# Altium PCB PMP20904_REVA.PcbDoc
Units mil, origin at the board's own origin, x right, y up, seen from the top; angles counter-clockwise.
Board outline 2450 x 1750 mil, 4 copper layers (Top Layer, Signal Layer 1, Signal Layer 2, Bottom Layer), stack 84.834 mil thick; 63 components, 24 nets, 129 pads, 79 vias.
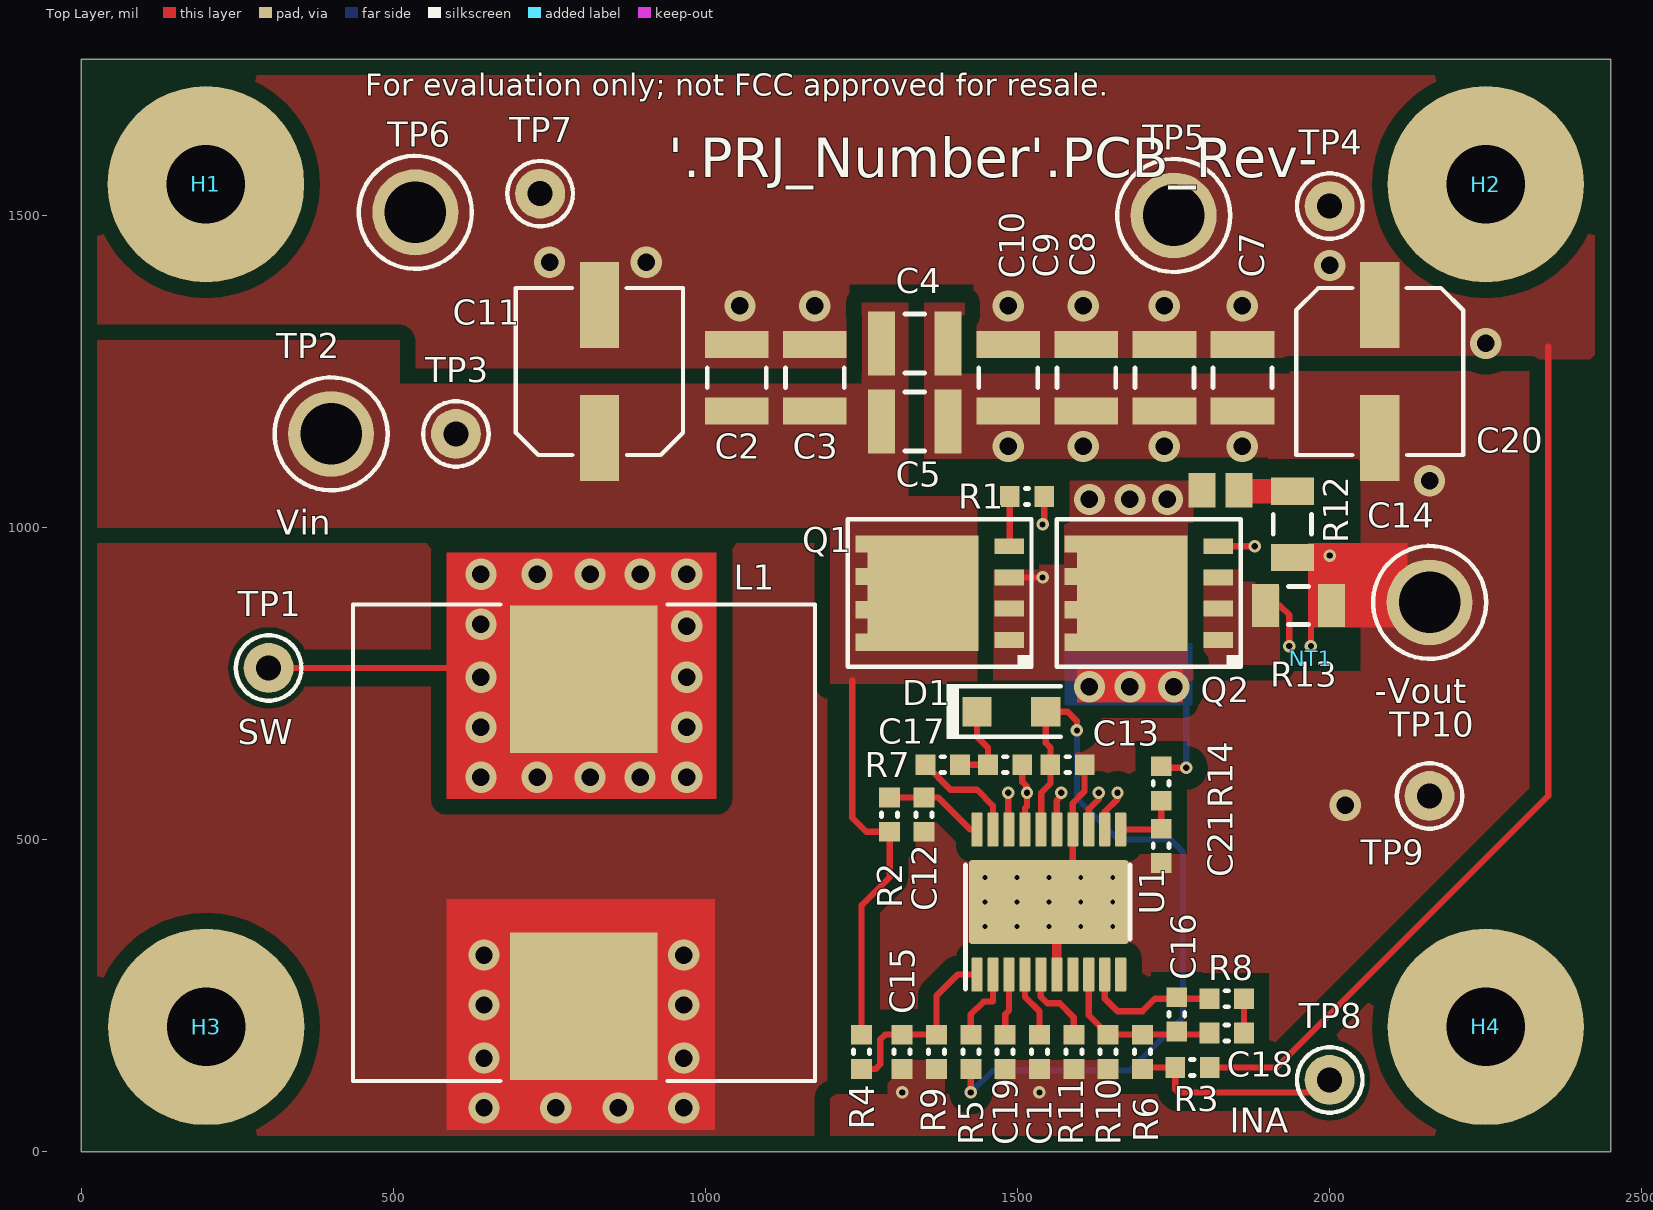
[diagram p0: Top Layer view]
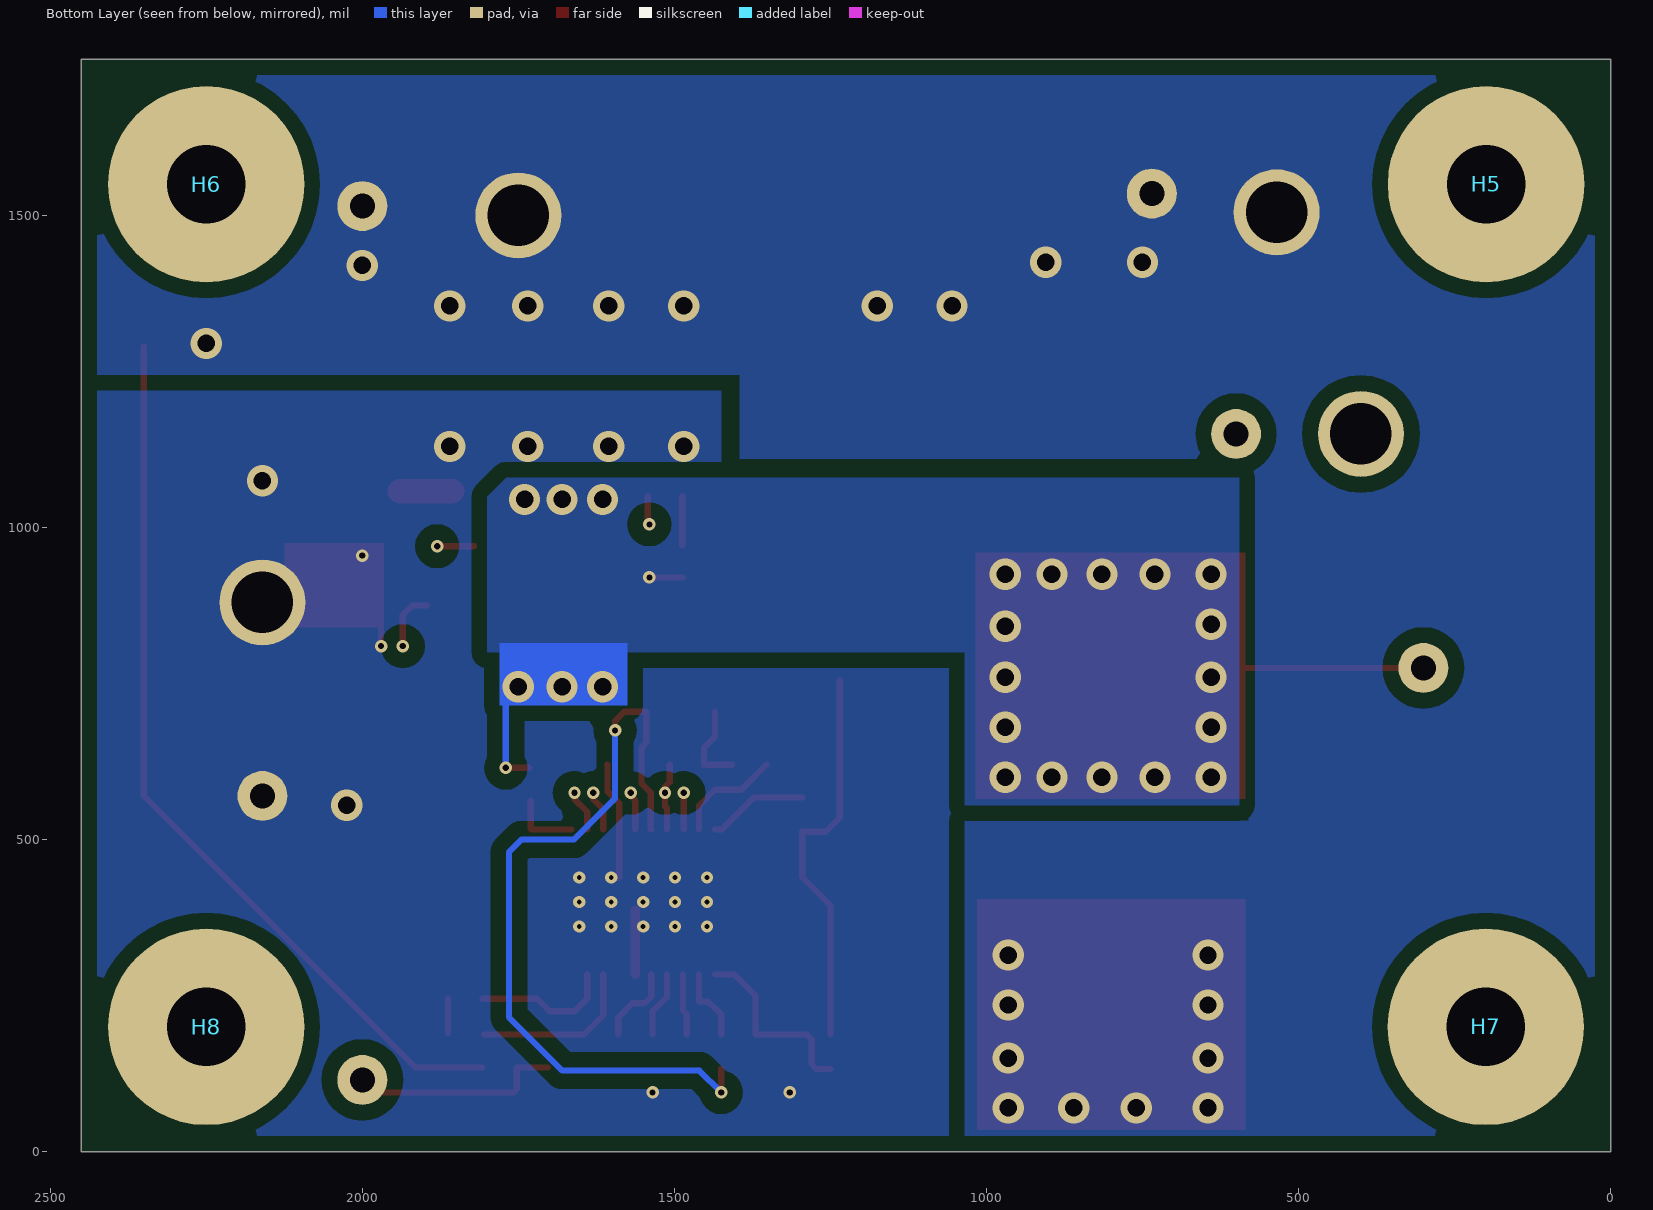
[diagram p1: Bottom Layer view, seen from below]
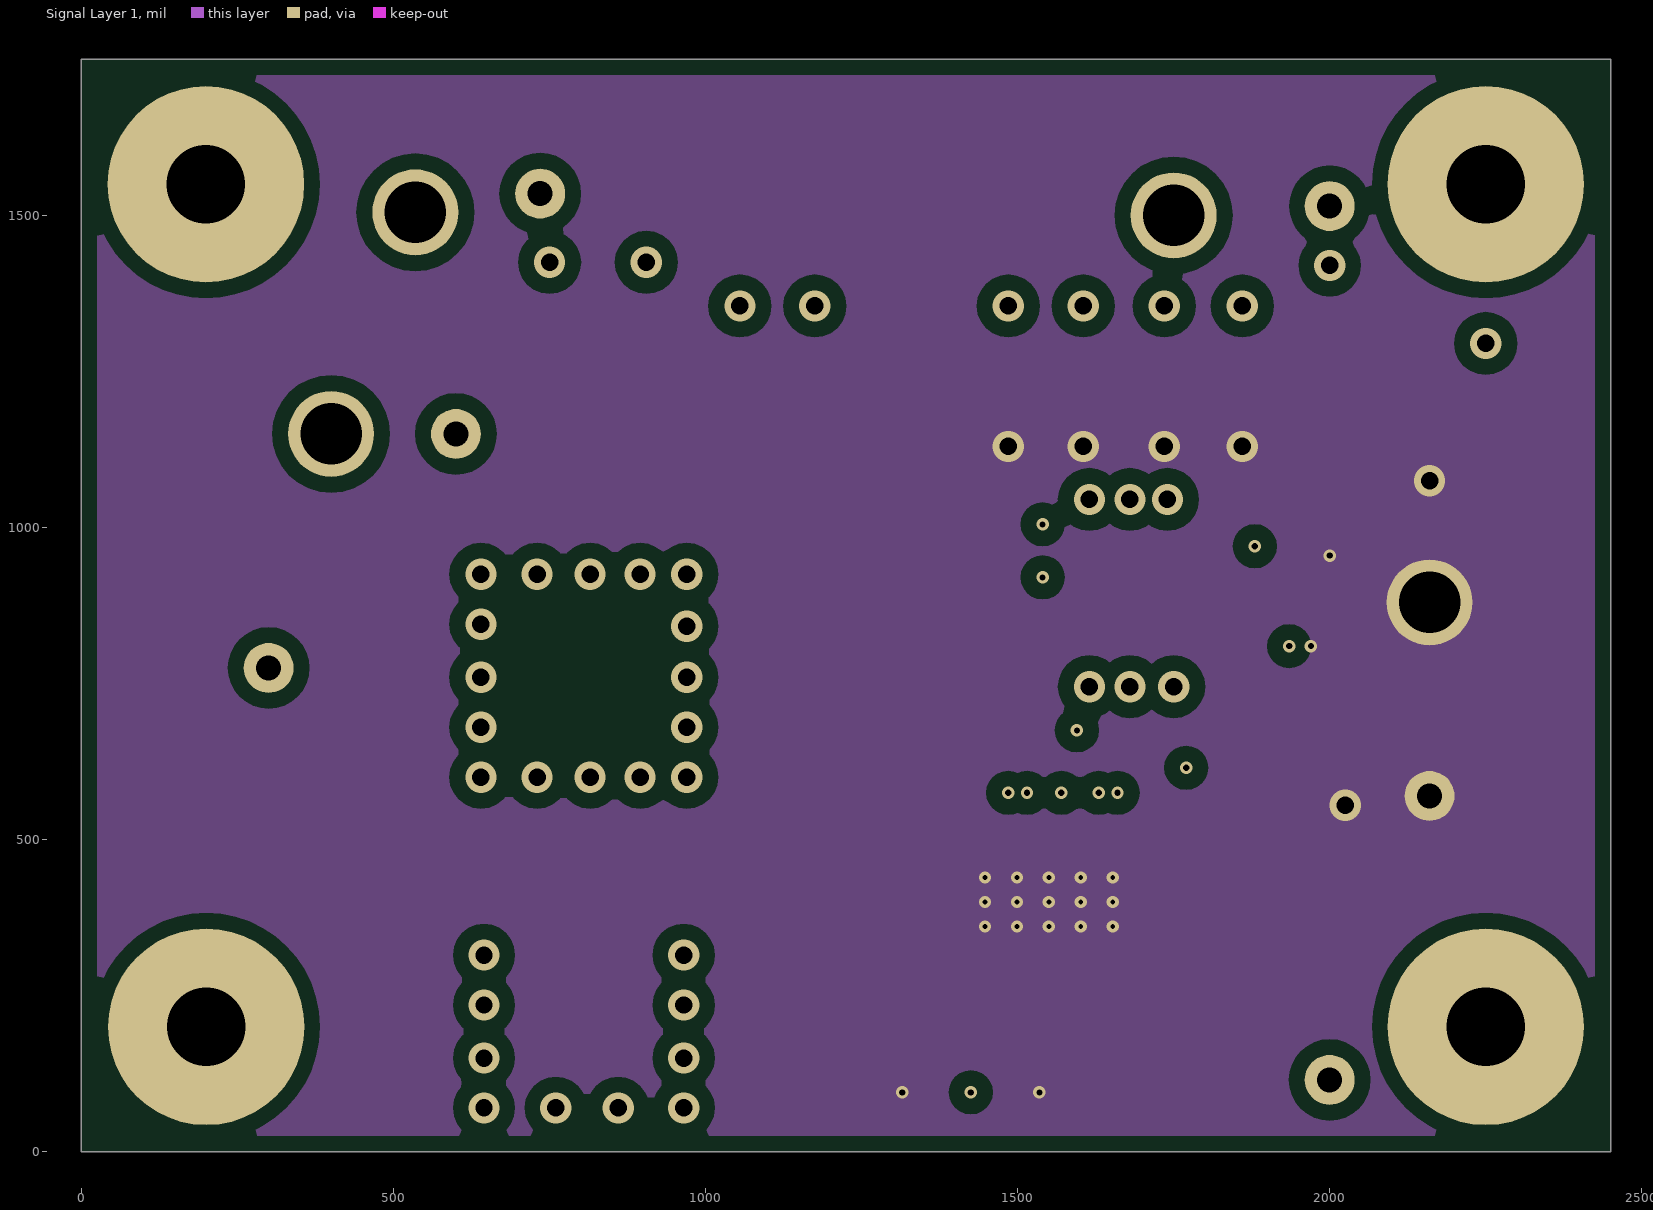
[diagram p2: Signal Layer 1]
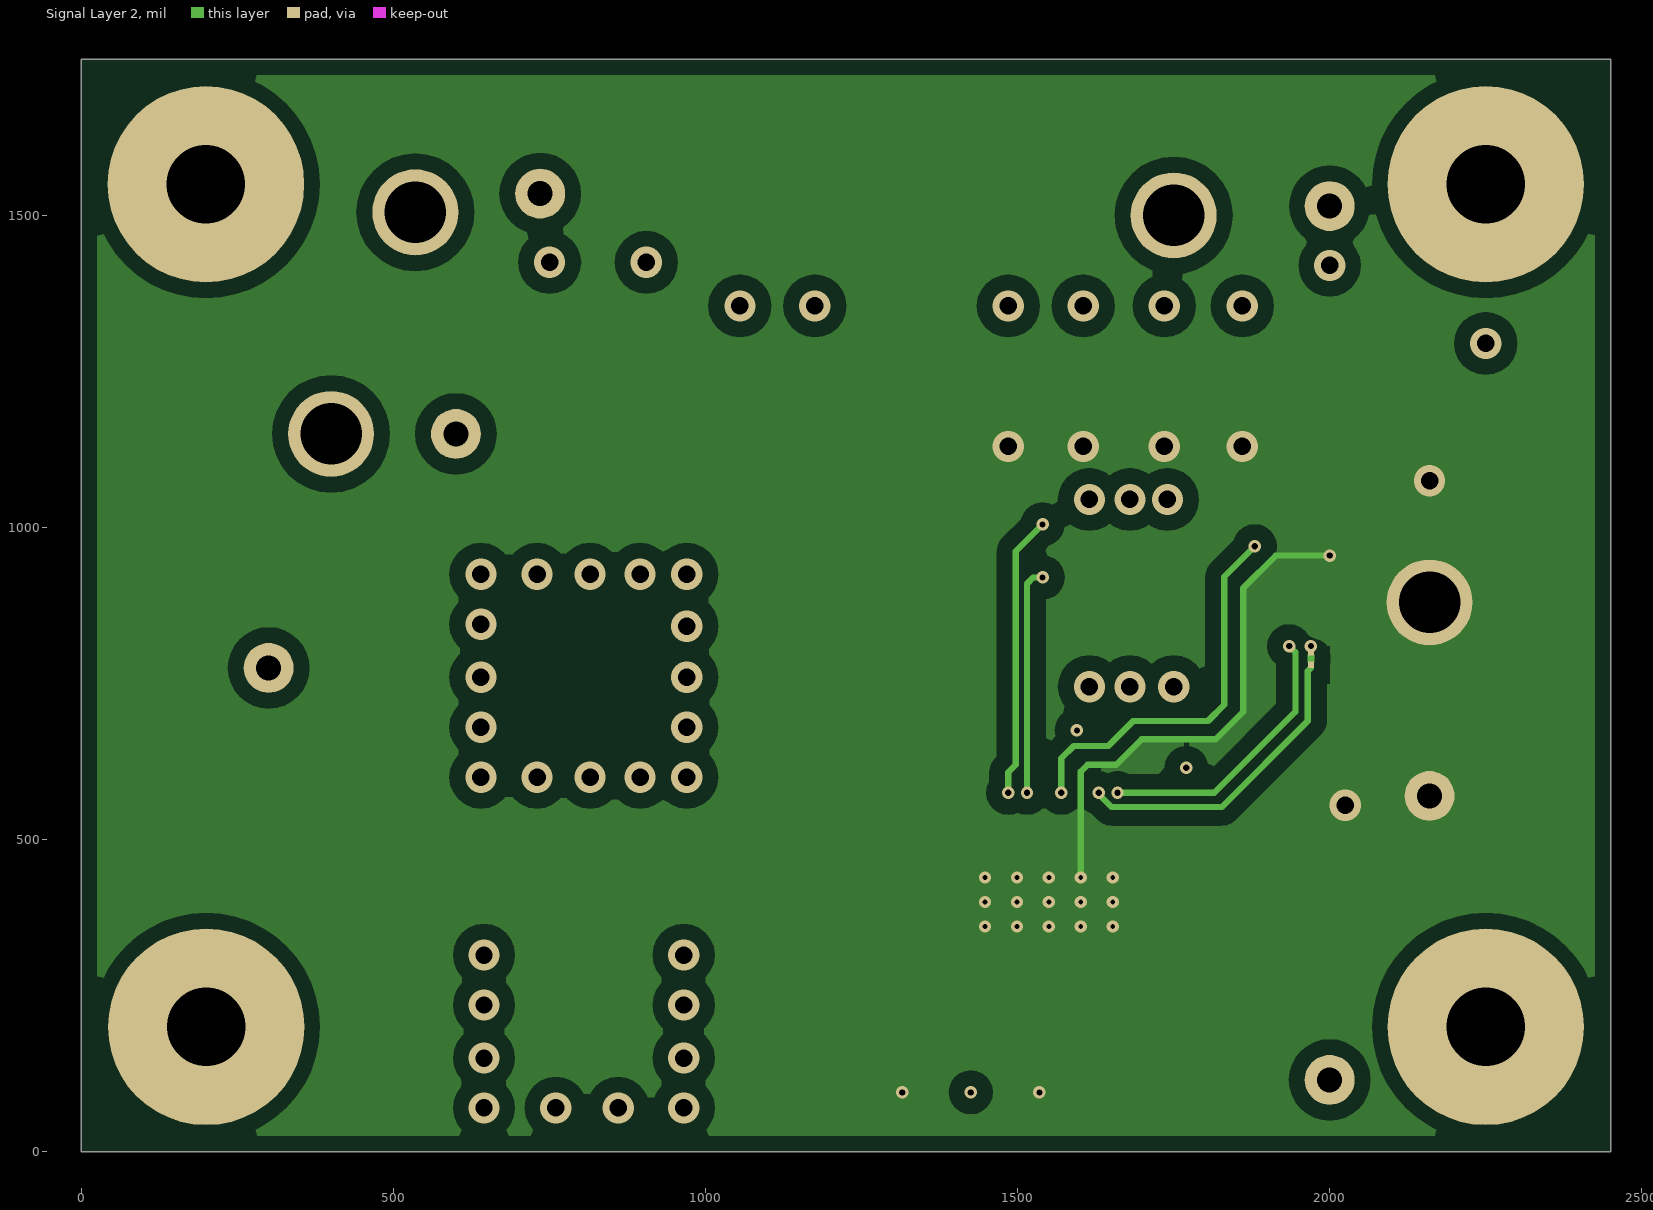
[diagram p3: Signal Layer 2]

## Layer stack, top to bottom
Top Solder: solder mask 0.4, Solder Resist, Dk 3.5
Top Layer: signal copper 1.4
Dielectric1: core 59.2, FR-4, Dk 4.8
Signal Layer 1: signal copper 1.417
Dielectric 2: dielectric 10, Dk 4.2
Signal Layer 2: signal copper 1.417
Dielectric 3: dielectric 10, Dk 4.2
Bottom Layer: signal copper 1.4
Bottom Solder: solder mask 0.4, Solder Resist, Dk 3.5

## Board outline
0,0 2450,0 2450,1750 0,1750

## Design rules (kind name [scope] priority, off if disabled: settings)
AcuteAngle [All] p1: minimum=4.50000000000000E+0001 checktracksonly=FALSE
AssemblyTestPointUsage [All] p1: valid=2
BoardOutlineClearance BoardOutlineClearance_MountingHoles [OnCopper and InComponentClass('Mounting Holes')] p1: gap=40
BoardOutlineClearance BoardOutlineClearance_Poly [OnCopper and IsPoly] p2: gap=25
BoardOutlineClearance [OnCopper and Not InComponentClass('Logo') and not InComponentClass('FiducialMark') and not InRegion(1000,500,4000,800) and not InPoly] p3: gap=75
Clearance Clearance_Keepouts [((IsTrack Or IsArc) And Not InPoly) And IsFree and IsKeepOut vs ((IsTrack Or IsArc) And Not InPoly) And IsFree and IsKeepOut] p1: gap=0
Clearance Clearance_Poly [InPolygon] p2: gap=25
Clearance [All] p3: gap=7.87
ComponentClearance ComponentClearance_MountingHoles_FiducialMarks [InComponentClass('Mounting Holes') vs InComponentClass('FiducialMark')] p1: gap=50 collisioncheckmode=3 verticalgap=10 showdistances=FALSE
ComponentClearance ComponentClearance_Shunt [InComponentClass('Header') vs InComponentClass('Shunt')] p2: gap=0 collisioncheckmode=3 verticalgap=0 showdistances=FALSE
ComponentClearance ComponentClearance_Logo [InComponentClass('Logo')] p3: gap=50 collisioncheckmode=3 verticalgap=10 showdistances=FALSE
ComponentClearance ComponentClearance_ScrewToNut [(HasFootprint('NY PMS 440 0025 PH')) vs (HasFootprint('Keystone_1902C'))] p4: gap=5 collisioncheckmode=3 verticalgap=10 showdistances=FALSE
ComponentClearance ComponentClearance_MountingHoles [InComponentClass('Mounting Holes')] p5: gap=50 collisioncheckmode=3 verticalgap=100000 showdistances=FALSE
ComponentClearance ComponentClearance_SmallPassives [HasFootprint('0201*') or HasFootprint('0402*') or HasFootprint('0508') or HasFootprint('0603*') or HasFootprint('0612') or HasFootprint('0805*') or HasFootprint('0815*') or HasFootprint('0830*') or HasFootprint('1206*') or HasFootprint('1210*') or HasFootprint('1808*') or HasFootprint('1812*') or HasFootprint('1825*') or HasFootprint('2010*') or HasFootprint('2220*') or HasFootprint('2225*') or HasFootprint('2512*') or HasFootprint('2728*') or HasFootprint('3518*') vs HasFootprint('0201*') or HasFootprint('0402*') or HasFootprint('0508') or HasFootprint('0603*') or HasFootprint('0612') or HasFootprint('0805*') or HasFootprint('0815*') or HasFootprint('0830*') or HasFootprint('1206*') or HasFootprint('1210*') or HasFootprint('1808*') or HasFootprint('1812*') or HasFootprint('1825*') or HasFootprint('2010*') or HasFootprint('2220*') or HasFootprint('2225*') or HasFootprint('2512*') or HasFootprint('2728*') or HasFootprint('3518*')] p6: gap=14.96 collisioncheckmode=3 verticalgap=10 showdistances=FALSE
ComponentClearance ComponentClearance_THtoSMT [IsThruComponent vs IsSMTComponent] p7: gap=40 collisioncheckmode=3 verticalgap=30 showdistances=FALSE
ComponentClearance ComponentClearance_THtoTH [IsThruComponent vs IsThruComponent] p8: gap=30 collisioncheckmode=3 verticalgap=30 showdistances=FALSE
ComponentClearance [All] p9: gap=30 collisioncheckmode=3 verticalgap=10 showdistances=FALSE
DiffPairsRouting [All] p1: maxlimit=100 minlimit=10 mostfreqgap=10 toplayer_minwidth=15 toplayer_maxwidth=15 toplayer_prefwidth=15 midlayer1_minwidth=15 midlayer1_maxwidth=15 midlayer1_prefwidth=15 midlayer2_minwidth=15 midlayer2_maxwidth=15 midlayer2_prefwidth=15 bottomlayer_minwidth=15 bottomlayer_maxwidth=15 bottomlayer_prefwidth=15 maxuncoupledlength=1000
FabricationTestPointUsage TestPointUsage [All] p1: valid=2 allowmultiple=FALSE
FabricationTestpoint Testpoint [All] p1: side=3 testpointundercomponent=TRUE minsize=40 maxsize=100 preferedsize=60 minholesize=0 maxholesize=40 preferedholesize=32 testpointgrid=1 allowsidetop=TRUE allowsidebottom=TRUE usegrid=TRUE gridtolerance=0.01
FanoutControl Fanout_LCC [IsLCC] p1: bgadir=Out bgaviamode=Centered fanoutstyle=Auto fanoutdirection=Alternating viagrid=1 // Fanout_LCC (Default Rule)
FanoutControl Fanout_BGA [IsBGA] p2: bgadir=Out bgaviamode=Centered fanoutstyle=Auto fanoutdirection=Alternating viagrid=1 // Fanout_BGA (Default Rule)
FanoutControl Fanout_Default [All] p4: bgadir=Out bgaviamode=Centered fanoutstyle=Auto fanoutdirection=Alternating viagrid=1 // Fanout_Default (Default Rule)
FanoutControl Fanout_Small [(CompPinCount < 5)] p5: bgadir=Out bgaviamode=Centered fanoutstyle=Auto fanoutdirection=OutThenIn viagrid=1 // Fanout_Small (Default Rule)
HoleSize [All] p1: absolutevalues=TRUE maxlimit=251 minlimit=7.87 maxpercent=80.000 minpercent=20.000
MinimumAnnularRing MinimumAnnularRing_ThermalPadVias [IsVia and InAnyComponent] p1: minimumring=5
MinimumAnnularRing [All] p2: minimumring=4.99
MinimumSolderMaskSliver MinimumSolderMaskSliver_Logo [InComponentClass('Logo') vs InComponentClass('Logo')] p1: minsoldermaskwidth=0.7
MinimumSolderMaskSliver [All] p2: minsoldermaskwidth=3.94
PlaneConnect [All] p1: planeconnectstyle=Direct reliefexpansion=10 reliefentries=4 reliefconductorwidth=10 reliefairgap=10
PolygonConnect [All] p1: connectstyle=Direct reliefconductorwidth=10 reliefentries=4 polygonreliefangle="90 Angle" airgapwidth=10
RoutingVias ThermalPadVias [IsVia and InAnyComponent] p1: holewidth=7.87 width=19.68 viastyle="Through Hole" minholewidth=7.87 minwidth=19.68 maxholewidth=12.99 maxwidth=23.62
RoutingVias [All] p2: holewidth=16 width=34 viastyle="Through Hole" minholewidth=7.87 minwidth=26 maxholewidth=40 maxwidth=65
SilkToBoardRegionClearance [Not ((IsComment or IsDesignator) And (Hide <> 'False')) and not InRegion(1000,500,4000,800)] p1:
SilkToSilkClearance SilkToSilkClearance_Pb-FreeLogo [(HasFootprint('Pb-Free_Overlay_Medium') OR HasFootprint('Pb-Free_Overlay_Small')) vs (HasFootprint('Pb-Free_Overlay_Medium') OR HasFootprint('Pb-Free_Overlay_Small'))] p1: silktosilkclearance=0
SilkToSilkClearance [All] p2: silktosilkclearance=4
SilkToSolderMaskClearance SilkToComponentPadClearance [(IsPad or IsFill or IsRegion) and InAnycomponent] p1: minsilkscreentomaskgap=5 clearancetoexposedcopper=TRUE
SilkToSolderMaskClearance "Silk to Solder Mask Opening" [All] p2: minsilkscreentomaskgap=4 clearancetoexposedcopper=FALSE
SolderMaskExpansion [All] p1: expansion=1.97
Width [All] p1: maxlimit=100 minlimit=6 preferedwidth=10 checkconnectedcopper=TRUE
15 further rules are at their usual default settings.

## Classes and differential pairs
component class PMP20904_REVA: C1 C2 C3 C4 C5 C7 C8 C9 C10 C11 C12 C13 C14 C15 C16 C17 C18 C19 C20 C21 D1 L1 NT1 Q1 Q2 R1 R2 R3 R4 R5 R6 R7 R8 R9 R10 R11 R12 R13 R14 TP1 TP2 TP3 TP4 TP5 TP6 TP7 TP8 TP9 TP10 U1
component class AssemblyNote: ZZ1 ZZ2 ZZ3 ZZ4
component class PMP20904_REVA_Hardware: H1 H2 H3 H4 H5 H6 H7 H8 Logo2 ZZ1 ZZ2 ZZ3 ZZ4
component class "Mounting Holes": H1 H2 H3 H4

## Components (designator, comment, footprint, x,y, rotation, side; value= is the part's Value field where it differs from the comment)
C1 "GRM188R71E104KA01D" 0603L 1535,160 r270 top
C2 "UMK325AB7106KM-T" 1210L 1050,1240 r90 top
C3 "UMK325AB7106KM-T" 1210L 1175,1240 r90 top
C4 "GRM32ER71K475KE14L" 1210L 1335,1295 r0 top
C5 "GRM32ER71K475KE14L" 1210L 1335,1170 r0 top
C7 "UMK325AB7106KM-T" 1210L 1860,1240 r270 top
C8 "UMK325AB7106KM-T" 1210L 1735,1240 r270 top
C9 "UMK325AB7106KM-T" 1210L 1610,1240 r270 top
C10 "UMK325AB7106KM-T" 1210L 1485,1240 r270 top
C11 "UUD1V680MCL1GS" SM_RADIAL_6.3BMM 830,1250 r90 top
C12 "CGA3E3X7R1H474M080AE" 0603L 1350,540 r270 top
C13 "GRM188R71C105KE15D" 0603L 1580,620 r0 top
C14 "DNP" 0805L 1825,1060 r0 top
C15 "GRM1885C1H470JA01D" 0603L 1315,160 r270 top
C16 "GRM188R71H472KA01D" 0603L 1755,220 r90 top
C17 "CGA3E3X7R1H474M080AE" 0603L 1480,620 r0 top
C18 "GRM188R71H473KA61D" 0603L 1835,190 r0 top
C19 "CGA3E3X7R1H474M080AE" 0603L 1480,160 r270 top
C20 "UUD1V680MCL1GS" SM_RADIAL_6.3BMM 2080,1250 r270 top
C21 "GRM1885C1H821JA01D" 0603L 1730,490 r270 top
D1 "PMEG6010CEH,115" SOD-123F 1490,705 r0 top
H1 "NY PMS 440 0025 PH" "NY PMS 440 0025 PH" 199.47,1550 r0 top locked
H2 "NY PMS 440 0025 PH" "NY PMS 440 0025 PH" 2250,1550 r0 top locked
H3 "NY PMS 440 0025 PH" "NY PMS 440 0025 PH" 200,200 r0 top locked
H4 "NY PMS 440 0025 PH" "NY PMS 440 0025 PH" 2250,200 r0 top locked
H5 "1902C" Keystone_1902C 199.47,1550 r180 bottom locked
H6 "1902C" Keystone_1902C 2250,1550 r180 bottom locked
H7 "1902C" Keystone_1902C 200,200 r180 bottom locked
H8 "1902C" Keystone_1902C 2250,200 r180 bottom locked
L1 "74435571500" WE-HCB_1890 805,495 r270 top
Logo2 "FCC disclaimer" FCC_disclaimer 2350,3380 r0 top
NT1 "Net-Tie" Net-Tie_10mil 1970,790 r270 top net-tie
Q1 "BSC097N06NSATMA1" PG-TDSON-8 1375,895 r180 top
Q2 "BSC097N06NSATMA1" PG-TDSON-8 1710,895 r180 top
R1 "CRCW06030000Z0EA" 0603L 1515,1050 r180 top
R2 "CRCW06033R90JNEA" 0603L 1295,540 r270 top
R3 "CRCW06038R06FKEA" 0603L 1780,135 r0 top
R4 "CRCW060349K9FKEA" 0603L 1250,160 r90 top
R5 "DNP" 0603L 1425,160 r90 top
R6 "CRCW06035K11FKEA" 0603L 1700,160 r270 top
R7 "CRCW06030000Z0EA" 0603L 1380,620 r180 top
R8 "CRCW06032K55FKEA" 0603L 1835,245 r0 top
R9 "CRCW06033K32FKEA" 0603L 1370,160 r90 top
R10 "CRCW0603174RFKEA" 0603L 1645,160 r90 top
R11 "CRCW060312K1FKEA" 0603L 1590,160 r90 top
R12 "DNP" 1206L#1 1940,1025 r90 top
R13 "WSL12068L000FEA" 1206L#2 1950,875 r180 top
R14 "CRCW0603232KFKEA" 0603L 1730,590 r90 top
TP1 "SW" Keystone5002 300,775 r90 top
TP2 "Vin" Keystone1502-2 400,1150 r0 top
TP3 "Vin" Keystone5000 600,1150 r90 top
TP4 "GND" Keystone5001 2000,1515 r90 top
TP5 "GND" Keystone1502-2 1750,1500 r0 top
TP6 "GND" Keystone1502-2 535,1505 r0 top
TP7 "GND" Keystone5001 735,1535 r90 top
TP8 "INA" Keystone5002 2000,115 r90 top
TP9 "-Vout" Keystone5000 2160,570 r90 top
TP10 "-Vout" Keystone1502-2 2160,880 r0 top
U1 "LM5117PMHX/NOPB" PWP0020A_N 1550,400 r90 top
ZZ1 "This Assembly Note is for PCB labels only" AssemblyNoteLabel 185,3938 r0 top
ZZ2 "These assemblies are ESD sensitive, ESD precautions shall be observed." AssemblyNote 185,3829.11 r0 top
ZZ3 "These assemblies must be clean and free from flux and all contaminants. Use of no clean flux is not acceptable." AssemblyNote 185,3740.56 r0 top
ZZ4 "These assemblies must comply with workmanship standards IPC-A-610 Class 2, unless otherwise specified." AssemblyNote 185,3652 r0 top

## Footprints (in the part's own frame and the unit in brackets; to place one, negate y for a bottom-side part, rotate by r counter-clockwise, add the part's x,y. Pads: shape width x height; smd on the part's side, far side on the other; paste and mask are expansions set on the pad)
0603L [mm] "0603 from SM-752 data"
  rect 0.8x0.85 smd: 1(-0.7,0) 2(0.7,0)
  silkscreen extent -0.07,-0.33 0.07,0.33, body extent -0.87,-0.47 0.87,0.47, height 1
0805L [mm] "0805 from SM-752 data"
  rect 1.1x1.4 smd: 1(-0.75,0) 2(0.75,0)
  body extent -1.1,-0.72 1.1,0.72, height 1.45
1206L#1 [mm] "1206 from SM-752 data"
  rect 1.1x1.75 smd: 1(-1.858,0) 2(0.842,0)
  silkscreen extent -0.91,-0.77 -0.11,0.77, body extent -2.21,-0.9 1.19,0.9, height 1.35
1206L#2 [mm] "1206 from SM-752 data"
  rect 1.1x1.75 smd: 1(-1.35,0) 2(1.35,0)
  silkscreen extent -0.4,-0.77 0.4,0.77, body extent -1.7,-0.9 1.7,0.9, height 1.35
1210L [mm] "1210 from SM-752 data"
  rect 1.1x2.6 smd: 1(-1.35,0) 2(1.35,0)
  silkscreen extent -0.4,-1.2 0.4,1.2, body extent -1.7,-1.35 1.7,1.35, height 1.35
AssemblyNote [mil] "Assembly Note"
AssemblyNoteLabel [mil] "Assembly Note for PCB Labels"
FCC_disclaimer [mil]
Keystone1502-2 [mm] "Double Turret"
  round 3.5 hole 2.5: 1(0,0)
  silkscreen extent -2.3,-2.3 2.3,2.3, body extent -1.6,-1.6 1.59,1.6, height 5.62
Keystone5000 [mil] "For Keystone 500x miniature loop terminals"
  round 80 hole 40: 1(0,0)
  silkscreen extent -52,-52 52,52, body extent -49,-49 49,49, height 182
Keystone5001 [mil] "For Keystone 500x miniature loop terminals"
  round 80 hole 40: 1(0,0)
  silkscreen extent -52,-52 52,52, body extent -49,-49 49,49, height 182
Keystone5002 [mil] "For Keystone 500x miniature loop terminals"
  round 80 hole 40: 1(0,0)
  silkscreen extent -52,-52 52,52, body extent -49,-49 49,49, height 182
Keystone_1902C [mil] "Hex Standoff, 4-40 threaded, nylon"
  body extent -145,-126 146,126, height 501
Net-Tie_10mil [mil] "10mil net tie, no solder mask opening, no solder paste"
  rect 10x10 on Mid2 paste-5 mask-5: 1(-10,0) 2(10,0)
  Signal Layer 2 region: -6,5 6,5 6,-5 -6,-5
"NY PMS 440 0025 PH" [mm] "4-40 nylon screw and mounting hole"
  round 8 hole 3.2: 1(0,0)
  body extent -3.3,-3.3 3.3,3.3, height 2.69
PG-TDSON-8 [mm] "Infineon recommended land pattern"
  rect 1.2x0.65 smd: 1(-2.825,1.905) 2(-2.825,0.635) 3(-2.825,-0.635) 4(-2.825,-1.905)
  rect 0.5x0.7 smd: 5(3.175,-2) 6(3.175,-0.675) 7(3.175,0.675) 8(3.175,2)
  rect 4.5x4.7 smd paste-2.25: 9(0.675,0)
  silkscreen extent -3.74,-3 3.74,3, body extent -3.18,-2.89 3.18,2.9, height 1.1
PWP0020A_N [mm] "TSOP, 20-Leads, Body 6.5x4.4mm, Pitch 0.65mm, Exposed Pad, IPC Medium Density"
  rrect22% 1.4x0.45 smd: 1(-2.95,2.925) 2(-2.95,2.275) 3(-2.95,1.625) 4(-2.95,0.975) 5(-2.95,0.325) 6(-2.95,-0.325) 7(-2.95,-0.975) 8(-2.95,-1.625) 9(-2.95,-2.275) 10(-2.95,-2.925) 11(2.95,-2.925) 12(2.95,-2.275) 13(2.95,-1.625) 14(2.95,-0.975) 15(2.95,-0.325) 16(2.95,0.325) 17(2.95,0.975) 18(2.95,1.625) 19(2.95,2.275) 20(2.95,2.925)
  rrect6% 3.4x6.5 smd paste-2 mask-2: 21(0,0)
  rrect3% 3.15x4.35 on Top Paste: 21(0,0)
  rrect3% 3.15x4.35 on Top Solder: 21(0,0)
  silkscreen extent -3.55,-3.3 1.5,3.4, body extent -3.21,-3.25 3.21,3.25, height 1
SM_RADIAL_6.3BMM [mm] "Nichicon 6.3x7.7"
  rect 3.5x1.6 smd: 1(-2.7,0) 2(2.7,0)
  silkscreen extent -3.4,-3.4 3.4,3.4, body extent -3.4,-3.4 3.4,3.4, height 8
SOD-123F [mm] "NXP recommended land pattern"
  rect 1.2x1.2 smd paste-0.05: 1(-1.4,0) 2(1.4,0)
  silkscreen extent -2.64,-1.12 2.01,1.12, body extent -1.8,-0.85 1.8,0.85, height 1.2
WE-HCB_1890 [mm] "WURTH ELEKTRONIK"
  rect 6x6 smd: 1(-6.65,0) 2(6.65,0)
  silkscreen extent -9.7,-9.4 9.7,9.4, body extent -9.65,-9.35 9.65,9.35, height 9.2

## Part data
C1: "CAP, CERM, 0.1 µF, 25 V, +/- 10%, X7R, 0603"
C2 C3 C7 C8 C9 C10: "CAP, CERM, 10 µF, 50 V, +/- 10%, X7R, 1210"
C4 C5: "CAP, CERM, 4.7 µF, 80 V, +/- 10%, X7R, 1210"
C11 C20: "CAP, AL, 68 µF, 35 V, +/- 20%, 0.34 ohm, SMD"
C12 C17 C19: "CAP, CERM, 0.47 µF, 50 V, +/- 20%, X7R, AEC-Q200 Grade 1, 0603"
C13: "CAP, CERM, 1 µF, 16 V, +/- 10%, X7R, 0603"
C14: library part GRM2165C2A101JA01D, "CAP, CERM, 100 pF, 100 V, +/- 5%, C0G/NP0, 0805"
C15: "CAP, CERM, 47 pF, 50 V, +/- 5%, C0G/NP0, 0603"
C16: "CAP, CERM, 4700 pF, 50 V, +/- 10%, X7R, 0603"
C18: "CAP, CERM, 0.047 µF, 50 V, +/- 10%, X7R, 0603"
C21: "CAP, CERM, 820 pF, 50 V, +/- 5%, C0G/NP0, 0603"
D1: "Diode, Schottky, 60 V, 1 A, SOD-123F"
H1 H2 H3 H4: "Machine Screw, Round, #4-40 x 1/4, Nylon, Philips panhead"
H5 H6 H7 H8: "Standoff, Hex, 0.5\"L #4-40 Nylon"
L1: "Inductor, Shielded Drum Core, Ferrite, 15 µH, 14 A, 0.009 ohm, SMD"
Logo2: library part FCC_disclaimer, "FCC_disclaimer"
NT1: "Single point connection between nets."
Q1 Q2: "MOSFET, N-CH, 60 V, 46 A, PG-TDSON-8"
R1 R7: "RES, 0, 5%, 0.1 W, 0603"
R2: "RES, 3.9, 5%, 0.1 W, 0603"
R3: "RES, 8.06, 1%, 0.1 W, 0603"
R4: "RES, 49.9 k, 1%, 0.1 W, 0603"
R5: library part CRCW060349K9FKEA, "RES, 49.9 k, 1%, 0.1 W, 0603"
R6: "RES, 5.11 k, 1%, 0.1 W, 0603"
R8: "RES, 2.55 k, 1%, 0.1 W, 0603"
R9: "RES, 3.32 k, 1%, 0.1 W, 0603"
R10: "RES, 174, 1%, 0.1 W, 0603"
R11: "RES, 12.1 k, 1%, 0.1 W, 0603"
R12: library part CRCW120610R0JNEA, "RES, 10, 5%, 0.25 W, 1206"
R13: "RES, 0.008, 1%, 0.25 W, AEC-Q200 Grade 0, 1206"
R14: "RES, 232 k, 1%, 0.1 W, 0603"
TP1 TP8: library part 5002, "Test Point, TH, Miniature, White"
TP2 TP5 TP6 TP10: library part 1502-2, "Terminal, Turret, TH, Double"
TP3 TP9: library part 5000, "Test Point, TH, Miniature, Red"
TP4 TP7: library part 5001, "Test Point, TH, Miniature, Black"
U1: "5.5-65V Wide Vin, Current Mode Synchronous Buck Controller with Analog Current Monitor, PWP0020A (TSSOP-20)"
ZZ1: library part AssemblyNoteLabel
ZZ2 ZZ3 ZZ4: library part AssemblyNote

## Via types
v1: diameter 50, hole 28, Top Layer to Bottom Layer, 48 vias
v2: diameter 20, hole 10, Top Layer to Bottom Layer, 16 vias
v3: diameter 19.68, hole 7.87, Top Layer to Bottom Layer, 9 vias
v4: diameter 19.68, hole 7.87, Top Layer to Bottom Layer, tented both sides, 6 vias

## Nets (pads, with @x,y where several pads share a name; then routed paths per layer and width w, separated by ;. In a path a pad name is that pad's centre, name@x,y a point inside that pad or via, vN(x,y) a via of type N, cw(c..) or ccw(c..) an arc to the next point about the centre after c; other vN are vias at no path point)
-VOUT: C1.2 C4.2 C5.2 C7.2 C8.2 C9.2 C10.2 C12.2 C13.2 C15.2 C19.2 C20.2 C21.2 NT1.1 R9.1 R10.1 R11.1 R12.1 R13.1 TP9.1 TP10.1 U1.6 U1.14 U1.21@1550,400 | length 1213
  Top Layer w10: U1.21@1588.39,438.39 U1.14 1588.39,558.39 1607.13,577.13 1607.13,619.57 C13.2 ; v2(1970,810) 1970,865 1980,875 R13.1
  Top Layer w15: U1.6 U1.21@1562.8,387.2
  Signal Layer 2 w10: v3(1601.18,439.37) 1601.18,609.06 1612.13,620 1657.79,620 1698.56,660.77 1817.11,660.77 1861.32,704.99 1861.32,903.1 1913.22,955 v2(2000,955)
  other v1: 2025,555 2160,1075 1485,1130 1605,1130 1735,1130 1860,1130
  other v2: 1315,95 1535,95
  other v3: 1498.82,360.63 1550,360.63 1601.18,360.63 1498.82,400 1550,400 1601.18,400 1498.82,439.37 1550,439.37
  other v4: 1447.64,360.63 1652.36,360.63 1447.64,400 1652.36,400 1447.64,439.37 1652.36,439.37
COMP: C16.2 R8.1 U1.9 | length 223
  Top Layer w10: U1.9 1639.57,245.43 1660,225 1700,225 1720,245 R8.1
CS: Q2.1 Q2.2 Q2.3 R13.2 U1.12 | length 609.7
  Top Layer w10: U1.12 1639.57,544.57 1660,565 v2(1660,575) ; R13.2 1920,875 1935,860 v2(1935,810)
  Signal Layer 2 w10: v2(1660,575) 1815,575 1945,705 1945,800 v2(1935,810)
CSG: NT1.2 U1.13 | length 560.5
  Top Layer w10: U1.13 1613.98,548.98 1630,565 v2(1630,575)
  Signal Layer 2 w10: v2(1630,575) 1630,572.65 1650.53,552.13 1827.13,552.13 1965,690 1965,770 1970,775 NT1.2
DEMB: R5.2 U1.2 | length 119.8
  Top Layer w10: R5.2 1425,220 1445.43,240.43 1460.43,240.43 U1.2
FB: C16.1 C18.1 R6.1 R10.2 U1.8 | length 269.1
  Top Layer w10: U1.8 1613.98,218.58 R10.2 R6.1 C18.1@1805,187.56
GND: C2.2 C3.2 C7.1 C8.1 C9.1 C10.1 C11.2 C20.1 L1.2 R3.2 TP4.1 TP5.1 TP6.1 TP7.1 | length 1442.6
  Top Layer w10: R3.2 1915,135 2350,570 2350,1290
  other v1: 645,70 760,70 860,70 965,70 645,150 965,150 645,235 965,235 645,315 965,315 2250,1295 1055,1355 1175,1355 1485,1355 1605,1355 1735,1355 1860,1355 2000,1420 750,1425 905,1425
HB: R7.2 U1.19 | length 173.5
  Top Layer w10: R7.2 1392.44,580 1435,580 1460.43,554.57 U1.19
HO: R1.1 U1.18 | length 556.7
  Top Layer w10: U1.18@1485,517.17 v2(1485,575) ; v2(1540,1005) 1542.56,1007.56 R1.1
  Signal Layer 2 w10: v2(1485,575) 1485,607.87 1497.13,620 1497.13,962.13 v2(1540,1005)
INA: R3.1 R6.2 TP8.1 | length 342.8
  Top Layer w10: R6.2@1702.56,135 R3.1 1752.44,100 1757.44,95 1980,95 TP8.1
LO: Q2.4 U1.15 | length 746.5
  Top Layer w10: U1.15 1562.8,562.8 1570,570 v2(1570,575) ; Q2.4 v2(1880,970)
  Signal Layer 2 w10: v2(1570,575) 1570,630 1590,650 1645,650 1685,690 1805,690 1831.06,716.06 1831.06,921.06 v2(1880,970)
NetC12_1: C12.1 R2.1 U1.20 | length 161.1
  Top Layer w10: R2.1 C12.1 1372.44,567.56 1423.86,516.14 U1.20
NetC14_2: C14.2 R12.2 | length 83.6
  Top Layer w40: C14.2@1856.38,1058.15 R12.2
NetC17_1: C17.1 D1.1 R7.1 | length 137.2
  Top Layer w10: R7.1 C17.1 1452.44,647.56 1434.88,665.12 D1.1
NetC18_2: C18.2 R8.2 | length 55
  Top Layer w10: C18.2 R8.2
NetQ1_4: Q1.4 R1.2 | length 78.8
  Top Layer w10: Q1.4@1487.44,971.22 R1.2
RAMP: C21.1 R14.1 U1.11 | length 110.3
  Top Layer w10: U1.11 1728.58,516.14 C21.1 R14.1
RES: C19.1 U1.3 | length 98.8
  Top Layer w10: C19.1 1480,220 1486.02,226.02 U1.3
RT: R11.2 U1.5 | length 129.7
  Top Layer w10: U1.5 1537.2,248.07 1547.64,237.64 1567.36,237.64 1590,215 R11.2
SS: C1.1 U1.4 | length 106
  Top Layer w10: U1.4 1511.61,248.39 1535,225 C1.1
SW: C14.1 C17.2 L1.1 Q1.1 Q1.2 Q1.3 Q2.5 Q2.6 Q2.7 Q2.8 Q2.9 R14.2 TP1.1 U1.17 | length 998.7
  Top Layer w10: TP1.1 v1@625,775 ; Q1.3 v2(1540,920) ; C17.2 1507.56,592.44 1515,585 v2(1515,575) 1515,553.54 1511.61,550.16 U1.17 ; R14.2@1732.56,615 v2(1770,615)
  Signal Layer 2 w10: v2(1515,575) 1515,910 1525,920 v2(1540,920)
  Bottom Layer w10: v2(1770,615) 1770,725
  other v1: 640,600 730,600 815,600 895,600 970,600 640,680 970,680 1615,745 1680,745 1750,745 640,760 970,760 970,841.89 640,845 640,925 730,925 815,925 895,925 970,925 1615,1045 1680,1045 1740,1045
UVLO: C15.1 R4.1 R9.2 U1.1 | length 307.6
  Top Layer w10: R4.1 1272.44,132.44 1280,140 1280,180 1287.56,187.56 R9.2 1370,250 1403.86,283.86 U1.1
VCC: C13.1 D1.2 R5.1 U1.16 | length 1275.6
  Top Layer w10: v2(1425,95) R5.1 ; U1.16 1537.87,516.81 1537.87,575.22 1552.44,589.79 C13.1 1552.44,647.56 1545.12,654.88 D1.2 1580,705 1595,690 v2(1595,675)
  Bottom Layer w10: v2(1425,95) 1460,130 1679.37,130 1765,215.63 1765,480 1745,500 1661.13,500 1595,566.13 v2(1595,675)
VIN: C2.1 C3.1 C4.1 C5.1 C11.1 Q1.5 Q1.6 Q1.7 Q1.8 Q1.9 R2.2 R4.2 TP2.1 TP3.1 | length 632.9
  Top Layer w10: 1235,755 1235,535 1257.56,512.44 R2.2 1295,440 1250,395 R4.2
pads on no net: H1.1 H2.1 H3.1 H4.1 U1.7 U1.10 U1.21@1550,400

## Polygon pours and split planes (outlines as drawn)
GND on Top Layer "GND" (solid, remove dead copper, pour order 26): 0,985 0,0 1195,0 1195,985
VIN on Top Layer "Vin" (solid, remove dead copper, pour order 2): 0,1230 0,1000 1200,1000 1200,750 1435.5,750 1435.5,1050 1325,1050 1325,1360 1250,1360 1250,1230 685,1230 510,1230 510,1300 335,1300 0,1300
SW on Top Layer "SW" (solid, remove dead copper, pour order 4): 1575,1075 1575,940 1450,940 1450,755.5 1781.69,755.5 1781.69,1075
-VOUT on Top Layer "-Vout" (solid, remove dead copper, pour order 6): 1345,1360 1345,1110 1755,1110 2020,1110 2045,1110 2050,1105 2050,750 2450,750 2450,1250 1415,1250 1415,1360
CS on Top Layer "CS" (solid, remove dead copper, pour order 8): 1790,940 1790,780 1920,780 1920,913.39 1861.61,913.39 1860,915 1857.24,917.76 1857.24,940
GND on Top Layer "GND" (solid, remove dead copper, pour order 10): 0,1750 0,1250 1230.12,1250 1230.12,1389.88 1430,1390 1430,1270.07 2450,1269.95 2450,1750
-VOUT on Top Layer "-Vout" (solid, remove dead copper, pour order 12): 1200,770 1200,0 2445,0 2450,5 2455,10 2455,770
-VOUT on Signal Layer 1 "-Vout" (solid, remove dead copper, pour order 14): 0,1750 0,0 2450,0 2450,1750
-VOUT on Signal Layer 2 "-Vout" (solid, remove dead copper, pour order 16): 0,1750 0,0 2445,0 2445,1750
GND on Bottom Layer "GND" (solid, remove dead copper, pour order 20): 0,1750 0,0 1035,0 1035,530 580,530 580,1110 1395,1110 1395,1245 2450,1245 2450,1745
SW on Bottom Layer "SW" (solid, remove dead copper, pour order 22): 595,1080 595,555 1035,555 1035,800 1800,800 1800,1049.41 1769.41,1080
-VOUT on Bottom Layer "-Vout" (solid, remove dead copper, pour order 24): 1425,1220 1425,1105 1045,1105 1045,0 2450,0 2450,1220

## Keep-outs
Keep-Out Layer:
  text ".Layer_Name" at 577,-858.49 h60

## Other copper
Top Layer:
  rectangle net SW: 585,565 1017.91,960
  rectangle net GND: 585,35 1015,405
  rectangle net SW: 1595,720 1765,776.89
  rectangle net -VOUT: 1965,840 2125,975
  text ".Layer_Name" at 577,-858.49 h60
Signal Layer 2:
  pour cut-out: 1985,810 1980,820 1970,825 1960,820 1955,810 1960,800 1969,796 1970,796 1980,800
Bottom Layer:
  rectangle net SW: 1575,715 1780,815
  text ".Layer_Name" at 577,-858.49 h60

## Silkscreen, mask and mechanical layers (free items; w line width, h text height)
Top Overlay:
  text "'.PRJ_Number'.PCB_Rev-" at 940,1540 h108.27
  text ".Layer_Name" at 577,-858.49 h60
Bottom Overlay:
  text ".Layer_Name" at 577,-858.49 h60
Top Paste:
  text ".Layer_Name" at 577,-858.49 h60
Bottom Paste:
  text ".Layer_Name" at 577,-858.49 h60
Top Solder:
  text ".Layer_Name" at 577,-858.49 h60
  text ".Layer_Name" at 577,-858.49 h60
Bottom Solder:
  text ".Layer_Name" at 577,-858.49 h60
Drill Guide:
  text ".Layer_Name" at 577,-858.49 h60
M1 Board Outline:
  the board outline again, w10
  text ".Layer_Name" at 577,-858.49 h60
M2 Board Dimensions:
  rectangle: 125,-400 500,-275
  rectangle: 0,-275 125,-150
  lines w7: 0,-275 1000,-275 ; 125,-400 125,-150 ; 250,-400 250,-150 ; 500,-400 500,-150 ; 750,-400 750,-150 ; 0,-400 0,-150 1000,-150 1000,-400 0,-400
  text ".Layer_Name" at 577,-858.49 h60
M3 3D STEP Top:
  text ".Layer_Name" at 577,-858.49 h60
M4 3D STEP Bottom:
  text ".Layer_Name" at 577,-858.49 h60
M5 Assembly Top:
  lines w10: -292,-930.17 6308,-930.17 ; -292,-726.83 6310,-726.83 ; -292,-523.5 -292,-1133.5 3713,-1133.5 6310,-1133.5 6310,-523.5 -291.5,-523.5 -291.5,-1133.5 1284,-1133.5 ; 2173,-1133.5 2173,-523.5 ; 3440,-726.83 3440,-523.5 ; 4280,-726.83 4280,-523.5 ; 4902,-1140 4902,-937.17
  text "COMPONENTS MARKED 'DNP' SHOULD NOT BE POPULATED." at 1153.5,-318.5 h60
  text "ASSEMBLY VARIANT:" at 1153,-434 h60
  text ".VariantName" at 2189,-434 h60
  text "PCB VIEWED FROM TOP SIDE" at -228.5,-655.67 h60
  text "BOARD #:" at 2248,-655.67 h60
  text ".PRJ_Number" at 2793.5,-655.67 h60
  text "REV:" at 3638,-655.67 h60
  text ".PCB_Rev" at 3929.5,-655.67 h60
  text "SVN REV:" at 4476,-655.67 h60
  text ".VersionControl_RevNumber" at 4982,-655.67 h60
  text "TID #:" at 2248,-859 h60
  text ".TID" at 2793.5,-859 h60
  text "PLOT NAME =" at -228.5,-1064.34 h60
  text ".plot_File_Name" at 577,-1064.34 h60
  text "GENERATED    :" at 2250,-1064.34 h60
  text ".Print_Date" at 3119.5,-1064.34 h60
  text ".Print_Time" at 3848.5,-1064.34 h60
  text "TEXAS INSTRUMENTS" at 5113,-1064.34 h60
M6 Assembly Bottom:
  lines w10: -292.5,-727.33 6309.5,-727.33 ; -290.5,-930.67 6309.5,-930.67 ; 1115.5,-1140.5 1115.5,-937.67 ; 1737.5,-727.33 1737.5,-524 ; 2577.5,-727.33 2577.5,-524 ; 3844.5,-1134 3844.5,-524 ; 4733.5,-1134 6309,-1134 6309,-524 -292.5,-524 -292.5,-1134 2304.5,-1134 6309.5,-1134 6309.5,-524
  text "COMPONENTS MARKED 'DNP' SHOULD NOT BE POPULATED." at 6102,-318 h60
  text ".VariantName" at 5058,-434 h60
  text "ASSEMBLY VARIANT:" at 6097,-434 h60
  text ".VersionControl_RevNumber" at 1035.5,-656.17 h60
  text "SVN REV:" at 1541.5,-656.17 h60
  text ".PCB_Rev" at 2088,-656.17 h60
  text "REV:" at 2379.5,-656.17 h60
  text ".PRJ_Number" at 3224,-656.17 h60
  text "BOARD #:" at 3769.5,-656.17 h60
  text "PCB VIEWED FROM BOTTOM SIDE" at 6246,-656.17 h60
  text ".TID" at 3224,-859.5 h60
  text "TID #:" at 3769.5,-859.5 h60
  text "TEXAS INSTRUMENTS" at 904.5,-1064.84 h60
  text ".Print_Time" at 2169,-1064.84 h60
  text ".Print_Date" at 2898,-1064.84 h60
  text "GENERATED    :" at 3767.5,-1064.84 h60
  text ".plot_File_Name" at 5440.5,-1064.84 h60
  text "PLOT NAME =" at 6246,-1064.84 h60
M9 Title Sheet:
  drawing of 57 lines, arcs and shapes, not listed
  text "1" at 739.84,8036.5 h70
  text "2" at 3235.5,8036.5 h70
  text "3" at 5724.84,8036.5 h70
  text "4" at 8231.51,8036.5 h70
  text "5" at 10730.5,8036.5 h70
  text "6" at 13235.5,8036.5 h70
  text "A" at -416.5,6893.5 h70
  text "A" at 14383.5,6893.5 h70
  text "B" at -416.5,4513.5 h70
  text "B" at 14383.5,4513.5 h70
  text "C" at -416.5,2138.5 h70
  text "C" at 14383.5,2138.5 h70
  text "PROJECT TITLE:" at 11343.5,277.5 h45
  text ".PRJ_Title" at 11393.5,144.17 h70
  text "DESIGNED FOR:" at 11343.5,-23.5 h45
  text ".PRJ_Customer" at 11393.5,-163.5 h70
  text "D" at -416.5,-231.5 h70
  text "D" at 14383.5,-231.5 h70
  text "FILE NAME:" at 11343.5,-323.5 h45
  text ".PCB_File_Name_No_Path" at 11393.5,-443.5 h70
  text "Texas Instruments (TI) and/or its licensors do not warrant the accuracy or completeness of this specification" at 6374,-605.34 h45
  text "ENGINEER:" at 11343.5,-613.5 h45
  text "LAYOUT BY:" at 12848.5,-613.5 h45
  text "or any information contained therein. TI and/or its licensors do not warrant that this design will meet" at 6329.01,-718 h45
  text ".PRJ_Engineer" at 11393.5,-768.49 h70
  text ".PCB_Layout" at 12899,-768.49 h70
  text "the specifications, will be suitable for your application or fit for any particular purpose, or will operate in" at 6329.01,-830.67 h45
  text ".Layer_Name" at 577,-858.49 h60
  text "ALTIUM DESIGNER VERSION:" at 12848.5,-923.5 h45
  text "an implementation. TI and/or its licensors do not warrant that the design is production worthy. You should" at 6329.01,-943.33 h45
  text "completely validate and test your design implementation to confirm the system functionality for your application." at 6374,-1056 h45
  text ".print_Scale" at 11393.5,-1056.83 h70
  text ".Application_BuildNumber" at 12899,-1056.83 h70
  text "1" at 739.84,-1263.5 h70
  text "2" at 3235.5,-1263.5 h70
  text "3" at 5724.84,-1263.5 h70
  text "4" at 8231.51,-1263.5 h70
  text "5" at 10730.5,-1263.5 h70
  text "6" at 13235.5,-1263.5 h70
M10 Fab Notes:
  drawing of 173 lines, arcs and shapes, not listed
  text "DESIGN INFORMATION" at 12378.02,6201 h60
  text "MIN. TRACK WIDTH:" at 11733.46,6021 h60
  text "8" at 12829.7,6021 h60
  text "MIL" at 12984.46,6021 h60
  text "MIN. CLEARANCE:" at 11733.46,5889 h60
  text "0.2" at 12769.7,5889 h60
  text "mm" at 12984.46,5889 h60
  text "MIN. VIA PAD SIZE:" at 11733.46,5757 h60
  text "24" at 12799.71,5757 h60
  text "MIL" at 12984.46,5757 h60
  text "0.05mm (2MIL)" at 12428.46,5615.29 h60
  text "MINIMUM ANNULAR RING" at 11404.23,5611 h60
  text "EXTERNAL" at 13136.46,5611 h60
  text "PER" at 11604.23,5493 h60
  text "IPC-D-275 CLASS 2 LEVEL C" at 11824.23,5493 h60
  text "MIL, HOLES" at 13312.46,5380.71 h60
  text "+/-" at 12920,5380 h60
  text "+/-" at 13774,5380 h60
  text "REGISTRATION TOLERANCES:" at 11404.23,5375 h60
  text "METAL" at 12604,5375 h60
  text "5" at 13180.2,5375 h60
  text "3" at 14013.2,5375 h60
  text "MIL" at 14129.46,5375 h60
  text "+/-" at 13774,5262 h60
  text "HOLE SIZE TOLERANCE (UNLESS OTHERWISE SPECIFIED):" at 11404.23,5257 h60
  text "3" at 14013.2,5257 h60
  text "MIL" at 14129.46,5257 h60
  text "MATERIAL:" at 11329.46,5047.54 h60
  text "FR-4 High Tg" at 12315.9,4907.21 h60
  text "FR-408" at 11750.46,4898.64 h60
  text "OTHER" at 13238.46,4898.64 h60
  text "X" at 12161,4895 h60
  text "62 MIL (1.6mm) +/-10%" at 12070.56,4735.92 h60
  text "THICKNESS:" at 11404.23,4731.64 h60
  text "X" at 11942.4,4731.64 h60
  text "OTHER" at 13355.46,4731.64 h60
  text "TOLERANCE:" at 11404.23,4573.64 h60
  text "X" at 12243.53,4573.64 h60
  text "ANSI IPC-6012 TYPE 3 CLASS 2" at 12430.48,4573.64 h60
  text "OTHER +/-" at 12430.46,4417.64 h60
  text "BOW & TWIST:" at 11404.23,4260.64 h60
  text "X" at 12243.53,4260.64 h60
  text "ANSI IPC-6012 TYPE 3 CLASS 2" at 12430.48,4260.64 h60
  text "OTHER +/-" at 12430.46,4102.13 h60
  text "DRILLING:" at 11329.46,3963.64 h60
  text "REFERENCE:" at 11404.23,3846.64 h60
  text "X" at 12052.46,3846.64 h60
  text "AS SHOWN" at 12239.46,3846.64 h60
  text "X" at 12953.46,3846.64 h60
  text "NC_DRILL FILES" at 13090.46,3846.64 h60
  text "PTH COPPER THICKNESS:" at 11404.23,3688.64 h60
  text "X" at 12534.46,3688.64 h60
  text "20-30 um" at 12671.46,3688.64 h60
  text "OTHER" at 13388.46,3688.64 h60
  text "BOARD FINISH:" at 11329.46,3529.64 h60
  text "SILKSCREEN:" at 11484.68,3411.64 h60
  text "X" at 12433.46,3411.64 h60
  text "TOP" at 12559.46,3411.64 h60
  text "X" at 12943.46,3411.64 h60
  text "BOTTOM" at 13070.46,3411.64 h60
  text "SILKSCREEN COLOR:" at 11484.68,3244.64 h60
  text "X" at 12432.42,3244.64 h60
  text "WHITE" at 12559.46,3244.64 h60
  text "OTHER" at 13070.46,3244.64 h60
  text "X" at 12563.42,3085.44 h60
  text "GREEN" at 12690.46,3085.44 h60
  text "OTHER" at 13308.46,3085.44 h60
  text "SOLDER RESIST COLOR:" at 11484.68,3074.64 h60
  text "X" at 12563.42,2915.44 h60
  text "MATTE" at 12690.46,2915.44 h60
  text "SEMI-GLOSS" at 13308,2914.8 h60
  text "IMMERSION GOLD (ENIG)" at 12390.46,2726.92 h60
  text "ENEPIG" at 13728,2723.64 h60
  text "SURFACE FINISH:" at 11329.46,2722.64 h60
  text "X" at 12203.51,2722.64 h60
  text "IMM. TIN/SILVER OR EQUIV" at 11659,2565.64 h60
  text "OTHER" at 13090.46,2565.64 h60
  text "ARRAY/PANEL:" at 11329.46,2386.64 h60
  text "CUT AND TRIM PER M1 BOARD OUTLINE" at 12390.46,2382.35 h60
  text "N.C. ROUTE" at 12390.46,2230.64 h60
  text "X" at 13069.46,2230.64 h60
  text "V. SCORE" at 13256.46,2230.64 h60
  text "CERTIFICATION:" at 11329.46,2093.64 h60
  text "MATERIALS AND WORKMANSHIP FOR ALL PCBS" at 12054.46,2093.64 h60
  text "TO MEET OR EXCEED THE REQUIREMENTS OF:" at 12054.46,1995.64 h60
  text "X" at 11680.96,1859.13 h60
  text "ANSI IPC-A-600F CLASS ->" at 11819.96,1859.13 h60
  text "X" at 13459.02,1859.13 h60
  text "2" at 13577.96,1859.14 h60
  text "1" at 13262.96,1857.64 h60
  text "3" at 13931.96,1857.64 h60
  text "X" at 12495.02,1699.64 h60
  text "RoHS" at 12631.96,1699.64 h60
  text "OTHER" at 13276.36,1699.64 h60
  text "PER ORDER" at 13673.42,1699.64 h60
  text "ALL BOARDS MUST MEET OR EXCEED UL94-V0 REQUIREMENTS." at 11357,1534 h60
  text "PCB MUST BEAR THE UL94V-0 UL REGISTERED MATERIAL ID NUMBER" at 11357,1414 h60
  text "ADDITIONAL REQUIREMENTS:" at 11329.46,1240.64 h60
  text "MICROSECTION:" at 11404.23,1125.64 h60
  text "YES" at 12309.96,1125.64 h60
  text "REQUIRED" at 13171.46,969.49 h60
  text "BARE BOARD ELEC. TEST:" at 11404.23,966.64 h60
  text "NONE" at 12709.96,966.64 h60
  text "X" at 13044.46,966.64 h60
  text "PER ORDER" at 13763.46,966.64 h60
  text ".Layer_Name" at 577,-858.49 h60
M11 Gerber Information:
  lines w10: -292,-930.17 6308,-930.17 ; -292,-726.83 6310,-726.83 ; -292,-523.5 -292,-1133.5 3713,-1133.5 6310,-1133.5 6310,-523.5 -291.5,-523.5 -291.5,-1133.5 1284,-1133.5 ; 2173,-1133.5 2173,-523.5 ; 3440,-726.83 3440,-523.5 ; 4280,-726.83 4280,-523.5 ; 4902,-1140 4902,-937.17
  text "ALL ARTWORK VIEWED FROM TOP SIDE" at -228.5,-655.67 h60
  text "BOARD #:" at 2248,-655.67 h60
  text ".PRJ_Number" at 2793.5,-655.67 h60
  text "REV:" at 3638,-655.67 h60
  text ".PCB_Rev" at 3929.5,-655.67 h60
  text "SVN REV:" at 4476,-655.67 h60
  text ".VersionControl_RevNumber" at 4982,-655.67 h60
  text "LAYER NAME =" at -228.5,-858.49 h60
  text "TID #:" at 2248,-859 h60
  text ".TID" at 2793.5,-859 h60
  text "PLOT NAME =" at -228.5,-1064.34 h60
  text ".plot_File_Name" at 577,-1064.34 h60
  text "GENERATED    :" at 2250,-1064.34 h60
  text ".Print_Date" at 3119.5,-1064.34 h60
  text ".Print_Time" at 3848.5,-1064.34 h60
  text "TEXAS INSTRUMENTS" at 5113,-1064.34 h60
M12 Stackup:
  drawing of 191 lines, arcs and shapes, not listed
  text "Layer" at 9790.34,7830 h60
  text "Name" at 10200.26,7830 h60
  text "Material" at 11130,7830 h60
  text "Thickness" at 11989.77,7830 h60
  text "Constant" at 12639.6,7830 h60
  text "Board Layer Stack" at 13209.46,7830 h60
  text "1" at 9790.34,7710 h60
  text "Top Overlay" at 10200.26,7710 h60
  text "2" at 9790.34,7590 h60
  text "Top Solder" at 10200.26,7590 h60
  text "Solder Resist" at 11130,7590 h60
  text "0.40mil" at 11989.77,7590 h60
  text "3.5" at 12639.6,7590 h60
  text "3" at 9790.34,7470 h60
  text "Top Layer" at 10200.26,7470 h60
  text "Copper" at 11130,7470 h60
  text "1.40mil" at 11989.77,7470 h60
  text "4" at 9790.34,7350 h60
  text "Dielectric1" at 10200.26,7350 h60
  text "FR-4" at 11130,7350 h60
  text "59.20mil" at 11989.77,7350 h60
  text "4.8" at 12639.6,7350 h60
  text "5" at 9790.34,7230 h60
  text "Bottom Layer" at 10200.26,7230 h60
  text "Copper" at 11130,7230 h60
  text "1.40mil" at 11989.77,7230 h60
  text "6" at 9790.34,7110 h60
  text "Bottom Solder" at 10200.26,7110 h60
  text "Solder Resist" at 11130,7110 h60
  text "0.40mil" at 11989.77,7110 h60
  text "3.5" at 12639.6,7110 h60
  text "7" at 9790.34,6990 h60
  text "Bottom Overlay" at 10200.26,6990 h60
  text ".Layer_Name" at 577,-858.49 h60
M13 Component Bodies Top:
  text ".Layer_Name" at 577,-858.49 h60
M14 Component Bodies Bottom:
  text ".Layer_Name" at 577,-858.49 h60
M15 Courtyards Top:
  text ".Layer_Name" at 577,-858.49 h60
M16 Courtyards Bottom:
  text ".Layer_Name" at 577,-858.49 h60
Drill Drawing:
  circle w10: c5363.8,2643.78 r27.66
  lines w10: 5336.14,2795.9 5391.46,2795.9 5363.8,2740.59 5336.14,2795.9 ; 5336.14,2865.04 5391.46,2865.04 5391.46,2920.36 5336.14,2920.36 5336.14,2865.04 ; 5336.14,2989.5 5363.8,3003.33 5391.46,2989.5 5377.63,3017.16 5391.46,3044.82 5363.8,3030.99 5336.14,3044.82 5349.97,3017.16 5336.14,2989.5 ; 5336.14,3127.79 5349.97,3127.79 5349.97,3113.96 5377.63,3113.96 5377.63,3127.79 5391.46,3127.79 5391.46,3155.45 5377.63,3155.45 5377.63,3169.28 5349.97,3169.28 5349.97,3155.45 5336.14,3155.45 5336.14,3127.79 ; 5336.14,3252.25 5349.97,3252.25 5363.8,3238.42 5377.63,3252.25 5391.46,3252.25 5377.63,3266.08 5391.46,3279.91 5377.63,3279.91 5363.8,3293.74 5349.97,3279.91 5336.14,3279.91 5349.97,3266.08 5336.14,3252.25
  lines w12: 5286,2578.79 8518.76,2578.79 ; 5286,3325.54 8518.76,3325.54 ; 5624.17,2454.33 5624.17,3450 ; 5956.28,2454.33 5956.28,3450 ; 6593.29,2454.33 6593.29,3450 ; 6852.64,2454.33 6852.64,3450 ; 7228.06,2454.33 7228.06,3450 ; 7951.91,2454.33 7951.91,3450 ; 5286,2454.33 8518.76,2454.33 8518.76,3450 5286,3450 5286,2454.33
  text "Symbol" at 5360.68,3362.88 h72
  text "Quantity" at 5661.51,3362.88 h72
  text "Finished Hole Size" at 5993.62,3362.88 h72
  text "Plated" at 6630.62,3362.88 h72
  text "Hole Type" at 6889.98,3362.88 h72
  text "Drill Layer Pair" at 7265.4,3362.88 h72
  text "Hole Tolerance" at 7989.25,3362.88 h72
  text "15" at 5661.51,3238.42 h60
  text "7.87mil (0.200mm)" at 5993.62,3238.42 h60
  text "PTH" at 6630.62,3238.42 h60
  text "Round" at 6889.98,3238.42 h60
  text "Top Layer - Bottom Layer" at 7265.4,3238.42 h60
  text "16" at 5661.51,3113.96 h60
  text "10.00mil (0.254mm)" at 5993.62,3113.96 h60
  text "PTH" at 6630.62,3113.96 h60
  text "Round" at 6889.98,3113.96 h60
  text "Top Layer - Bottom Layer" at 7265.4,3113.96 h60
  text "48" at 5661.51,2989.5 h60
  text "28.00mil (0.711mm)" at 5993.62,2989.5 h60
  text "PTH" at 6630.62,2989.5 h60
  text "Round" at 6889.98,2989.5 h60
  text "Top Layer - Bottom Layer" at 7265.4,2989.5 h60
  text "6" at 5661.51,2865.04 h60
  text "40.00mil (1.016mm)" at 5993.62,2865.04 h60
  text "PTH" at 6630.62,2865.04 h60
  text "Round" at 6889.98,2865.04 h60
  text "Top Layer - Bottom Layer" at 7265.4,2865.04 h60
  text "4" at 5661.51,2740.59 h60
  text "98.43mil (2.500mm)" at 5993.62,2740.59 h60
  text "PTH" at 6630.62,2740.59 h60
  text "Round" at 6889.98,2740.59 h60
  text "Top Layer - Bottom Layer" at 7265.4,2740.59 h60
  text "4" at 5661.51,2616.13 h60
  text "125.98mil (3.200mm)" at 5993.62,2616.13 h60
  text "PTH" at 6630.62,2616.13 h60
  text "Round" at 6889.98,2616.13 h60
  text "Top Layer - Bottom Layer" at 7265.4,2616.13 h60
  text "93 Total" at 5661.51,2491.67 h60
  text ".Layer_Name" at 577,-858.49 h60
M17 Embedded Cavity:
  text ".Layer_Name" at 577,-858.49 h60
M18 Embedded Assembly:
  text ".Layer_Name" at 577,-858.49 h60
M19 Embedded Keepout:
  text ".Layer_Name" at 577,-858.49 h60

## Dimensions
0,0 to 2450,0 on M2 Board Dimensions
0,0 to 0,1750 on M2 Board Dimensions
0,-400 to 1000,-400 on M2 Board Dimensions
